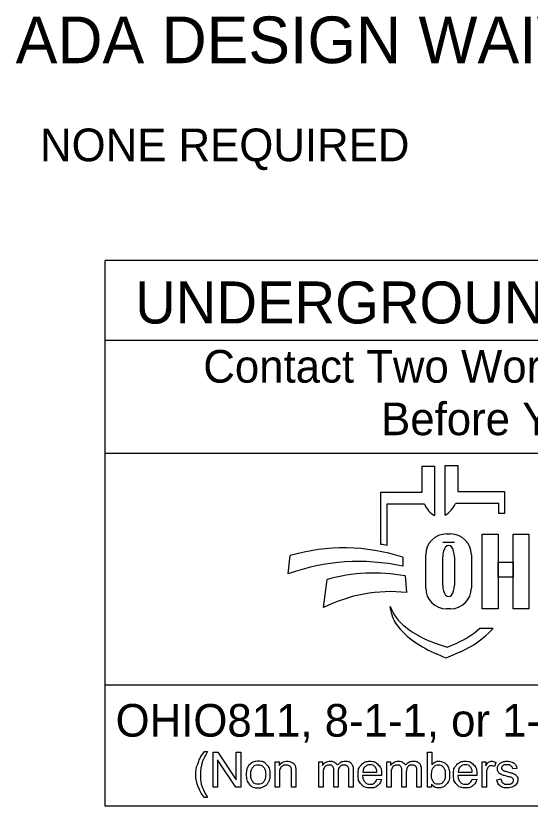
# Model space of a CAD drawing. Extents: x 0 to 42, y 0 to 22.
# Drawn here: x 1.995 to 4.196, y 2.143 to 5.529 of the extents above; entities that cross this region are included whole.
import ezdxf

# ---------------------------------------------------------------- set-up
doc = ezdxf.new("R2010")
doc.units = 0
doc.layers.add('SH_Data', color=7, linetype='Continuous')
doc.layers.add('SH_Text', color=7, linetype='Continuous')

msp = doc.modelspace()

# ---------------------------------------------------------------- linework, layer by layer
at = {"layer": 'SH_Data'}
for p, q in [((2.3775, 2.1428), (2.3775, 4.4803)), ((6.6275, 4.4803), (2.3775, 4.4803)), ((2.3775, 4.1387), (6.6275, 4.1387)), ((2.3775, 3.6553), (6.6275, 3.6553)), ((6.6275, 2.6607), (2.3775, 2.6607)), ((6.6275, 2.1428), (2.3775, 2.1428))]:
    msp.add_line(p, q, dxfattribs=at)
at = {"layer": 'SH_Text'}
for p, q in [((3.7335, 3.4883), (3.7335, 3.5998)), ((3.7335, 3.5998), (3.7872, 3.5998)), ((3.7872, 3.5998), (3.7872, 3.3877)), ((3.8329, 3.39), (3.8329, 3.6021)), ((3.8329, 3.6021), (3.8865, 3.6021)), ((3.8865, 3.6021), (3.8865, 3.4906)), ((3.5576, 3.2644), (3.5576, 3.4883)), ((3.5576, 3.4883), (3.7335, 3.4883)), ((3.8865, 3.4906), (4.0857, 3.4906)), ((4.0857, 3.4906), (4.0857, 3.3968)), ((3.5828, 3.4369), (3.5828, 3.26)), ((3.7439, 3.4369), (3.5828, 3.4369)), ((4.0625, 3.4392), (3.8761, 3.4392)), ((4.0625, 3.3968), (4.0625, 3.4392)), ((4.0857, 3.3968), (4.0625, 3.3968)), ((3.8385, 3.3091), (3.8551, 3.3091)), ((3.8718, 3.2721), (3.822, 3.2721)), ((3.7491, 3.0776), (3.7491, 3.2196)), ((3.9445, 3.2196), (3.9445, 3.0776)), ((3.1602, 3.1381), (3.1696, 3.2162)), ((3.6509, 3.2097), (3.6509, 3.1709)), ((3.822, 3.089), (3.822, 3.2114)), ((3.8718, 3.2114), (3.8718, 3.089)), ((3.6608, 3.1291), (3.6671, 3.0582)), ((3.312, 2.9936), (3.3267, 3.1137)), ((3.5997, 2.9807), (3.5967, 2.9986)), ((3.8551, 2.9882), (3.8385, 2.9882)), ((3.98, 2.9048), (4.0375, 2.9048)), ((3.7816, 2.8444), (3.841, 2.8239)), ((3.841, 2.8239), (3.8821, 2.8417)), ((3.835, 2.7769), (3.7976, 2.7934)), ((3.8983, 2.8044), (3.835, 2.7769))]:
    msp.add_line(p, q, dxfattribs=at)
for points in [[(3.991, 3.3081), (4.0589, 3.3081), (4.0589, 2.9881), (3.991, 2.9881)], [(4.1231, 3.3081), (4.1911, 3.3081), (4.1911, 2.9881), (4.1231, 2.9881)], [(4.0589, 3.1882), (4.1231, 3.1882), (4.1231, 3.1242), (4.0589, 3.1242)]]:
    msp.add_lwpolyline(points, close=True, dxfattribs=at)
for points in [[(2.8021, 2.3766), (2.8153, 2.3766)], [(2.8389, 2.2239), (2.8389, 2.3741), (2.8592, 2.3741), (2.9382, 2.2561), (2.9382, 2.3741), (2.9572, 2.3741), (2.9572, 2.2239), (2.9369, 2.2239), (2.8579, 2.3419), (2.8579, 2.2239), (2.8389, 2.2239)], [(3.7743, 2.2239), (3.7573, 2.2239), (3.7573, 2.3741), (3.7757, 2.3741), (3.7757, 2.3206)], [(3.1048, 2.2239), (3.1048, 2.3328), (3.1214, 2.3328), (3.1214, 2.3173)], [(3.2912, 2.2239), (3.2912, 2.3328), (3.3077, 2.3328), (3.3077, 2.3174)], [(3.5826, 2.2239), (3.5826, 2.3328), (3.5991, 2.3328), (3.5991, 2.3174)], [(3.9904, 2.2239), (3.9904, 2.3328), (4.007, 2.3328), (4.007, 2.3163)], [(4.0495, 2.3293), (4.043, 2.3122)], [(4.1394, 2.3046), (4.1213, 2.3022)], [(3.1233, 2.2833), (3.1233, 2.2239), (3.1048, 2.2239)], [(3.1932, 2.2908), (3.1932, 2.2239), (3.1748, 2.2239), (3.1748, 2.2901)], [(3.3097, 2.2803), (3.3097, 2.2239), (3.2912, 2.2239)], [(3.3743, 2.2871), (3.3743, 2.2239), (3.3559, 2.2239), (3.3559, 2.2946)], [(3.4388, 2.2986), (3.4388, 2.2239), (3.4203, 2.2239), (3.4203, 2.2924)], [(3.56, 2.2736), (3.4788, 2.2736)], [(3.4799, 2.2887), (3.5406, 2.2887)], [(3.601, 2.2803), (3.601, 2.2239), (3.5826, 2.2239)], [(3.6657, 2.2871), (3.6657, 2.2239), (3.6473, 2.2239), (3.6473, 2.2946)], [(3.7301, 2.2986), (3.7301, 2.2239), (3.7117, 2.2239), (3.7117, 2.2924)], [(3.968, 2.2736), (3.8868, 2.2736)], [(3.8879, 2.2887), (3.9486, 2.2887)], [(4.0088, 2.2809), (4.0088, 2.2239), (3.9904, 2.2239)], [(3.5404, 2.2591), (3.5595, 2.2567)], [(3.7743, 2.2375), (3.7743, 2.2239)], [(3.9484, 2.2591), (3.9675, 2.2567)], [(4.053, 2.2564), (4.0712, 2.2593)], [(2.8153, 2.1798), (2.8021, 2.1798)]]:
    msp.add_lwpolyline(points, dxfattribs=at)
for centre, radius, start, end in [((3.8353, 3.4736), 0.0985, 201.9296, 240.7469), ((3.7847, 3.476), 0.0985, 299.2531, 338.0704), ((3.8385, 3.2196), 0.0895, 90, 180), ((3.8551, 3.2196), 0.0895, 0, 90), ((3.4295, 2.4554), 0.8191, 79.2074, 81.0007), ((3.3997, 2.4302), 0.8191, 72.1402, 106.3144), ((3.4628, 2.2991), 0.8919, 77.8238, 109.8274), ((3.5267, 2.4094), 0.7322, 79.44, 105.8467), ((3.5987, 2.4262), 0.6357, 83.8248, 116.8021), ((3.8385, 3.0776), 0.0895, 180, 270), ((3.8551, 3.0776), 0.0895, 270, 0), ((3.7841, 3.0707), 0.2008, 201.0457, 232.5314), ((3.741, 3.0048), 0.1433, 189.6817, 216.0884), ((3.8747, 3.1022), 0.3088, 216.0884, 235.7167), ((3.9766, 3.3219), 0.5173, 232.5314, 241.794), ((3.7387, 3.1722), 0.3602, 293.4582, 312.0712), ((3.7387, 3.1722), 0.401, 293.4582, 317.8286), ((4.0412, 3.3465), 0.6044, 235.7167, 246.2325), ((3.8914, 3.1631), 0.3371, 241.794, 250.9821)]:
    msp.add_arc(centre, radius, start, end, dxfattribs=at)
for centre, start_param, end_param in [((3.8469, 3.2114), 4.712389, 7.853982), ((3.8469, 3.089), 1.570796, 4.712389)]:
    msp.add_ellipse(centre, major_axis=(0, 0.0484), ratio=0.514403, start_param=start_param, end_param=end_param, dxfattribs=at)
for points in [[(2.8021, 2.1798), (2.7869, 2.199), (2.7763, 2.2248), (2.7657, 2.2506), (2.7657, 2.2783), (2.7657, 2.3026), (2.7736, 2.325), (2.7829, 2.3509), (2.8021, 2.3766)], [(2.8153, 2.3766), (2.8029, 2.3553), (2.7989, 2.3462), (2.7927, 2.332), (2.7891, 2.3167), (2.7847, 2.2975), (2.7847, 2.2782), (2.7847, 2.2289), (2.8153, 2.1798)], [(2.9814, 2.2783), (2.9814, 2.3085), (2.9981, 2.3231), (3.0122, 2.3352), (3.0323, 2.3352), (3.0547, 2.3352), (3.069, 2.3205), (3.0832, 2.3058), (3.0832, 2.2799), (3.0832, 2.2589), (3.0769, 2.2469), (3.0706, 2.2348), (3.0586, 2.2282), (3.0466, 2.2215), (3.0323, 2.2215), (3.0095, 2.2215), (2.9954, 2.2362), (2.9814, 2.2508), (2.9814, 2.2783)], [(3.0003, 2.2783), (3.0003, 2.2574), (3.0094, 2.247), (3.0185, 2.2366), (3.0323, 2.2366), (3.046, 2.2366), (3.0551, 2.2471), (3.0642, 2.2575), (3.0642, 2.279), (3.0642, 2.2991), (3.0551, 2.3095), (3.0459, 2.3199), (3.0323, 2.3199), (3.0185, 2.3199), (3.0094, 2.3096), (3.0003, 2.2992), (3.0003, 2.2783)], [(3.1214, 2.3173), (3.1334, 2.3352), (3.156, 2.3352), (3.1659, 2.3352), (3.1741, 2.3316), (3.1823, 2.3281), (3.1864, 2.3224), (3.1905, 2.3166), (3.1922, 2.3087), (3.1932, 2.3036), (3.1932, 2.2908)], [(3.1748, 2.2901), (3.1748, 2.3013), (3.1726, 2.3069), (3.1705, 2.3125), (3.165, 2.3158), (3.1595, 2.3191), (3.1521, 2.3191), (3.1404, 2.3191), (3.1318, 2.3117), (3.1233, 2.3042), (3.1233, 2.2833)], [(3.3077, 2.3174), (3.3128, 2.3254), (3.3214, 2.3303), (3.3299, 2.3352), (3.3407, 2.3352), (3.3528, 2.3352), (3.3606, 2.3301), (3.3683, 2.3251), (3.3715, 2.3161), (3.3844, 2.3352), (3.4051, 2.3352), (3.4213, 2.3352), (3.43, 2.3262), (3.4388, 2.3172), (3.4388, 2.2986)], [(3.3559, 2.2946), (3.3559, 2.3069), (3.3514, 2.313), (3.3469, 2.3191), (3.3366, 2.3191), (3.3288, 2.3191), (3.3222, 2.315), (3.3156, 2.311), (3.3126, 2.3031), (3.3097, 2.2952), (3.3097, 2.2803)], [(3.4203, 2.2924), (3.4203, 2.3035), (3.4185, 2.3083), (3.4168, 2.3132), (3.412, 2.3162), (3.4073, 2.3191), (3.401, 2.3191), (3.3895, 2.3191), (3.3819, 2.3115), (3.3743, 2.3039), (3.3743, 2.2871)], [(3.5595, 2.2567), (3.555, 2.24), (3.5428, 2.2307), (3.5306, 2.2215), (3.5117, 2.2215), (3.4878, 2.2215), (3.4738, 2.2362), (3.4598, 2.2509), (3.4598, 2.2774), (3.4598, 2.3049), (3.474, 2.32), (3.4881, 2.3352), (3.5106, 2.3352), (3.5324, 2.3352), (3.5463, 2.3203), (3.5601, 2.3055), (3.5601, 2.2785), (3.5601, 2.2769), (3.56, 2.2736)], [(3.5406, 2.2887), (3.5394, 2.3025), (3.5337, 2.3094), (3.5249, 2.3201), (3.5108, 2.3201), (3.4981, 2.3201), (3.4894, 2.3115), (3.4808, 2.303), (3.4799, 2.2887)], [(3.5991, 2.3174), (3.6042, 2.3254), (3.6127, 2.3303), (3.6212, 2.3352), (3.6321, 2.3352), (3.6442, 2.3352), (3.6519, 2.3301), (3.6597, 2.3251), (3.6628, 2.3161), (3.6758, 2.3352), (3.6965, 2.3352), (3.7127, 2.3352), (3.7214, 2.3262), (3.7301, 2.3172), (3.7301, 2.2986)], [(3.6473, 2.2946), (3.6473, 2.3069), (3.6428, 2.313), (3.6383, 2.3191), (3.628, 2.3191), (3.6202, 2.3191), (3.6136, 2.315), (3.607, 2.311), (3.604, 2.3031), (3.601, 2.2952), (3.601, 2.2803)], [(3.7117, 2.2924), (3.7117, 2.3035), (3.7099, 2.3083), (3.7081, 2.3132), (3.7034, 2.3162), (3.6987, 2.3191), (3.6923, 2.3191), (3.6809, 2.3191), (3.6733, 2.3115), (3.6657, 2.3039), (3.6657, 2.2871)], [(3.7741, 2.2792), (3.7741, 2.2596), (3.7794, 2.2509), (3.7881, 2.2366), (3.8029, 2.2366), (3.815, 2.2366), (3.8238, 2.2471), (3.8326, 2.2576), (3.8326, 2.2784), (3.8326, 2.2998), (3.8241, 2.3099), (3.8157, 2.3201), (3.8038, 2.3201), (3.7917, 2.3201), (3.7829, 2.3096), (3.7741, 2.299), (3.7741, 2.2792)], [(3.7757, 2.3206), (3.7874, 2.3352), (3.8055, 2.3352), (3.8155, 2.3352), (3.8245, 2.3311), (3.8335, 2.3271), (3.8392, 2.3198), (3.845, 2.3124), (3.8483, 2.3021), (3.8516, 2.2918), (3.8516, 2.28), (3.8516, 2.252), (3.8378, 2.2368), (3.8239, 2.2215), (3.8046, 2.2215), (3.7853, 2.2215), (3.7743, 2.2375)], [(3.9675, 2.2567), (3.963, 2.24), (3.9508, 2.2307), (3.9386, 2.2215), (3.9196, 2.2215), (3.8958, 2.2215), (3.8818, 2.2362), (3.8678, 2.2509), (3.8678, 2.2774), (3.8678, 2.3049), (3.882, 2.32), (3.8961, 2.3352), (3.9186, 2.3352), (3.9404, 2.3352), (3.9543, 2.3203), (3.9681, 2.3055), (3.9681, 2.2785), (3.9681, 2.2769), (3.968, 2.2736)], [(3.9486, 2.2887), (3.9474, 2.3025), (3.9417, 2.3094), (3.9328, 2.3201), (3.9188, 2.3201), (3.9061, 2.3201), (3.8974, 2.3115), (3.8888, 2.303), (3.8879, 2.2887)], [(4.007, 2.3163), (4.0133, 2.3278), (4.0187, 2.3315), (4.0241, 2.3352), (4.0305, 2.3352), (4.0398, 2.3352), (4.0495, 2.3293)], [(4.043, 2.3122), (4.0363, 2.3162), (4.0295, 2.3162), (4.0235, 2.3162), (4.0187, 2.3125), (4.0139, 2.3089), (4.0119, 2.3024), (4.0088, 2.2926), (4.0088, 2.2809)], [(4.1213, 2.3022), (4.1201, 2.3106), (4.1142, 2.3153), (4.1083, 2.3201), (4.0975, 2.3201), (4.0848, 2.3201), (4.0794, 2.3159), (4.0739, 2.3116), (4.0739, 2.306), (4.0739, 2.3024), (4.0762, 2.2995), (4.0785, 2.2966), (4.0833, 2.2946), (4.086, 2.2936), (4.0996, 2.2899), (4.1192, 2.2847), (4.1269, 2.2813), (4.1347, 2.278), (4.1391, 2.2717), (4.1435, 2.2653), (4.1435, 2.2559), (4.1435, 2.2467), (4.1381, 2.2386), (4.1327, 2.2304), (4.1226, 2.226), (4.1124, 2.2215), (4.0996, 2.2215), (4.0784, 2.2215), (4.0672, 2.2303), (4.0561, 2.2391), (4.053, 2.2564)], [(4.0712, 2.2593), (4.0727, 2.2483), (4.0798, 2.2425), (4.0868, 2.2366), (4.0995, 2.2366), (4.1122, 2.2366), (4.1184, 2.2418), (4.1245, 2.247), (4.1245, 2.254), (4.1245, 2.2602), (4.1191, 2.2638), (4.1153, 2.2663), (4.1002, 2.2701), (4.0799, 2.2752), (4.072, 2.2789), (4.0642, 2.2827), (4.0601, 2.2893), (4.0561, 2.2959), (4.0561, 2.3038), (4.0561, 2.3111), (4.0594, 2.3173), (4.0628, 2.3235), (4.0685, 2.3276), (4.0728, 2.3308), (4.0803, 2.333), (4.0877, 2.3352), (4.0962, 2.3352), (4.109, 2.3352), (4.1187, 2.3315), (4.1284, 2.3278), (4.133, 2.3215), (4.1377, 2.3152), (4.1394, 2.3046)], [(3.4788, 2.2736), (3.4799, 2.2557), (3.489, 2.2462), (3.4981, 2.2366), (3.5117, 2.2366), (3.5219, 2.2366), (3.5291, 2.242), (3.5362, 2.2473), (3.5404, 2.2591)], [(3.8868, 2.2736), (3.8879, 2.2557), (3.897, 2.2462), (3.9061, 2.2366), (3.9197, 2.2366), (3.9299, 2.2366), (3.937, 2.242), (3.9442, 2.2473), (3.9484, 2.2591)]]:
    msp.add_open_spline(points, degree=3, dxfattribs=at)

# ---------------------------------------------------------------- texts
for s, height, p in [('ADA DESIGN WAIVERS', 0.2, (1.9944, 5.3256)), ('  NONE REQUIRED                          ', 0.14, (1.9944, 4.9056)), ('UNDERGROUND UTILITIES', 0.18, (2.5057, 4.2106)), ('Contact Two Working Days', 0.14, (2.7972, 3.9571)), ('Before You Dig', 0.14, (3.5583, 3.7321)), ('OHIO811, 8-1-1, or 1-800-362-2764', 0.14, (2.422, 2.4406))]:
    msp.add_text(s, height=height, dxfattribs=at).set_placement(p)

doc.saveas('drawing.dxf')
